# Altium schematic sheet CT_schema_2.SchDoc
size 523 x 486 mm
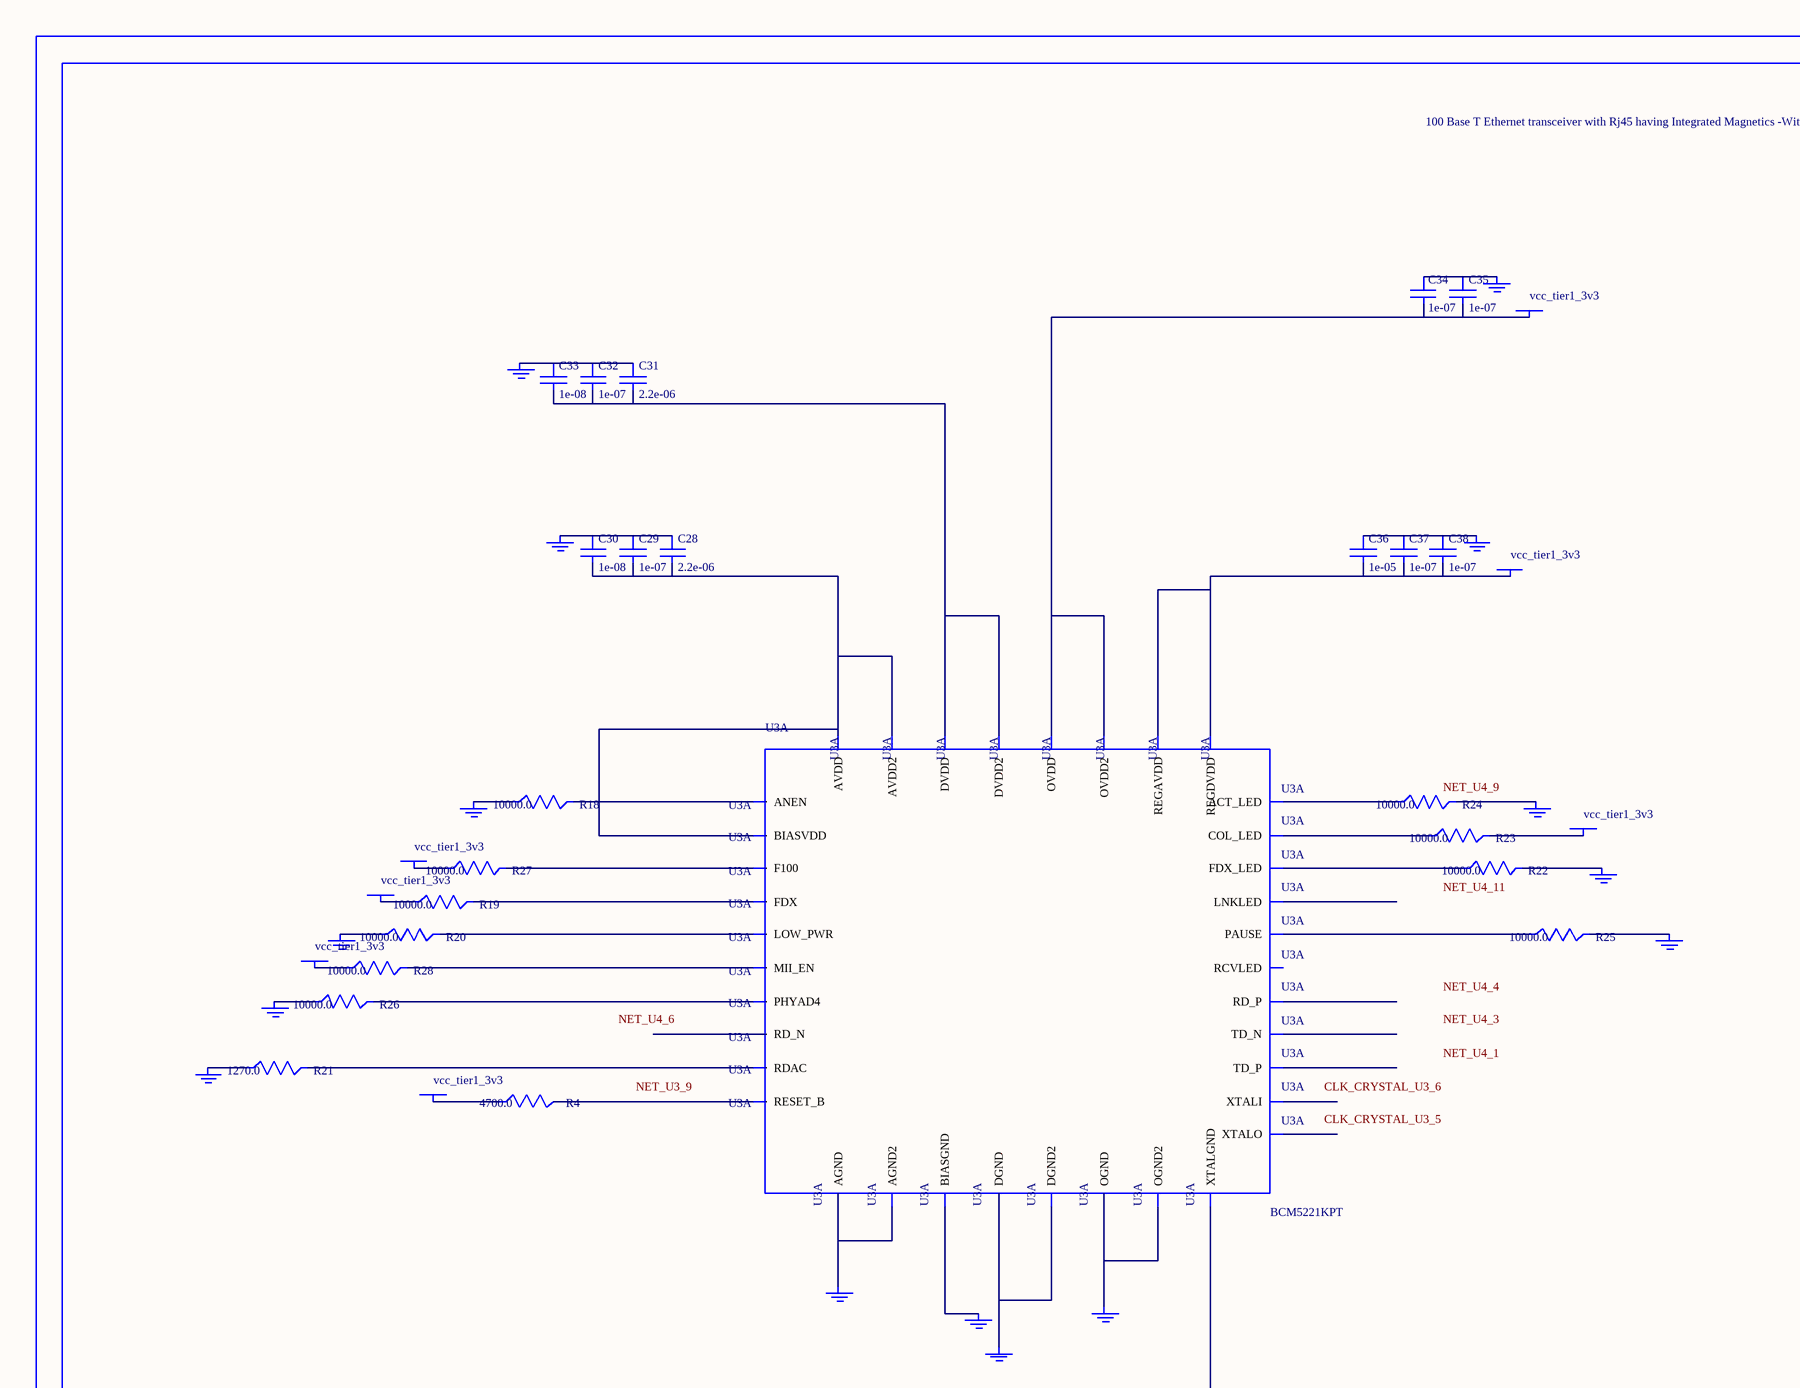
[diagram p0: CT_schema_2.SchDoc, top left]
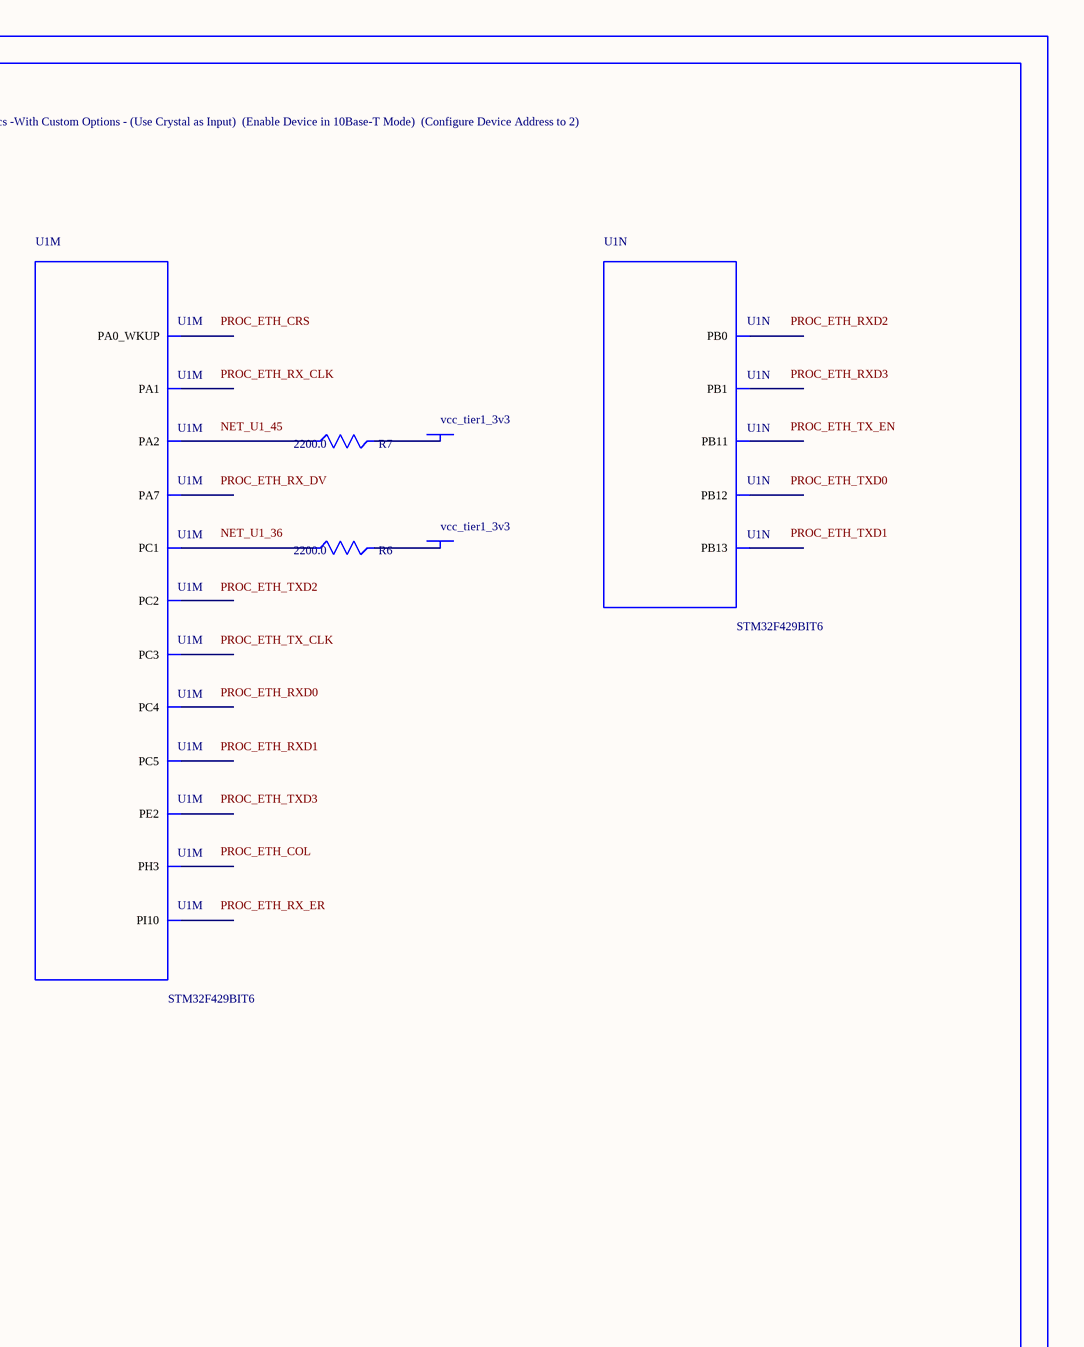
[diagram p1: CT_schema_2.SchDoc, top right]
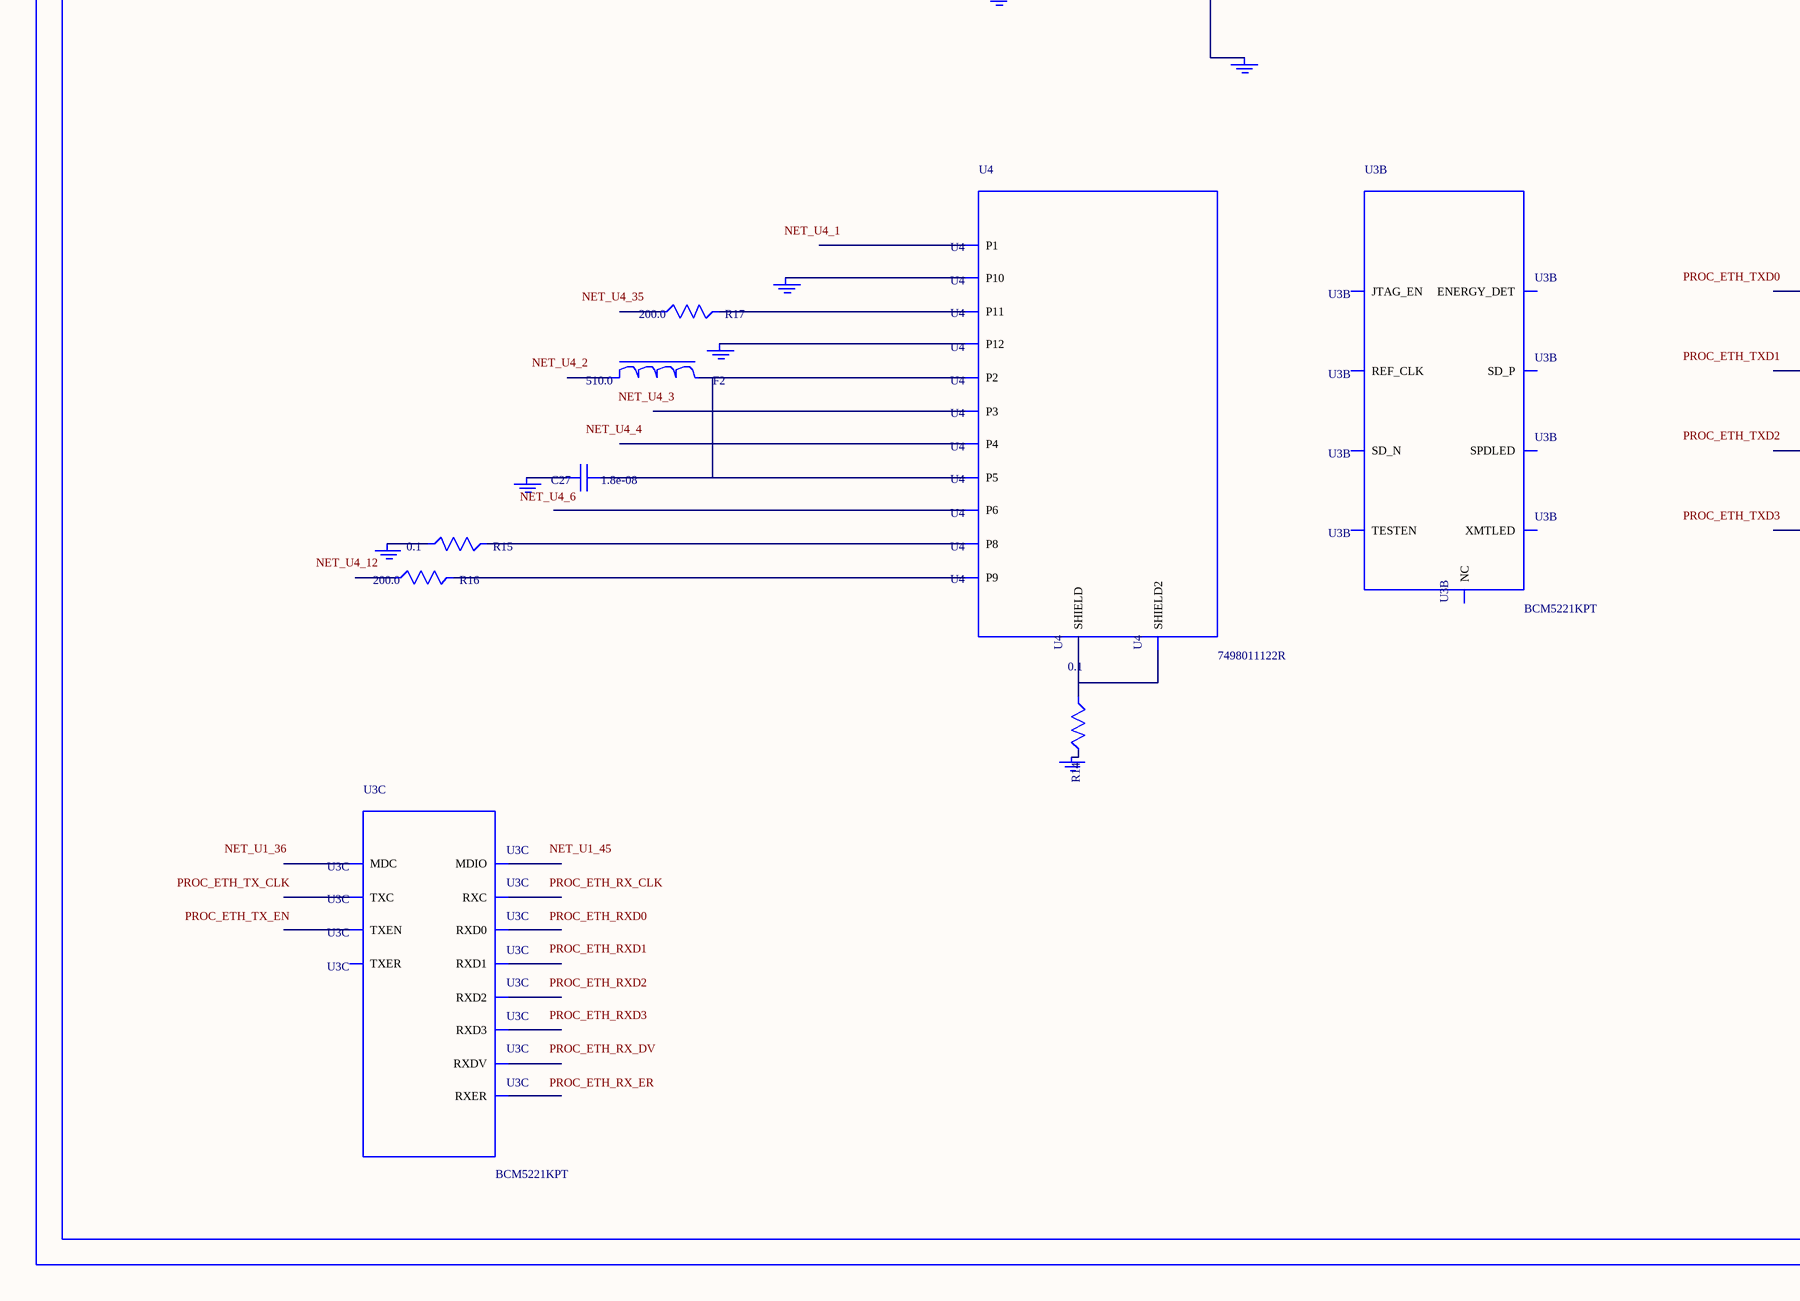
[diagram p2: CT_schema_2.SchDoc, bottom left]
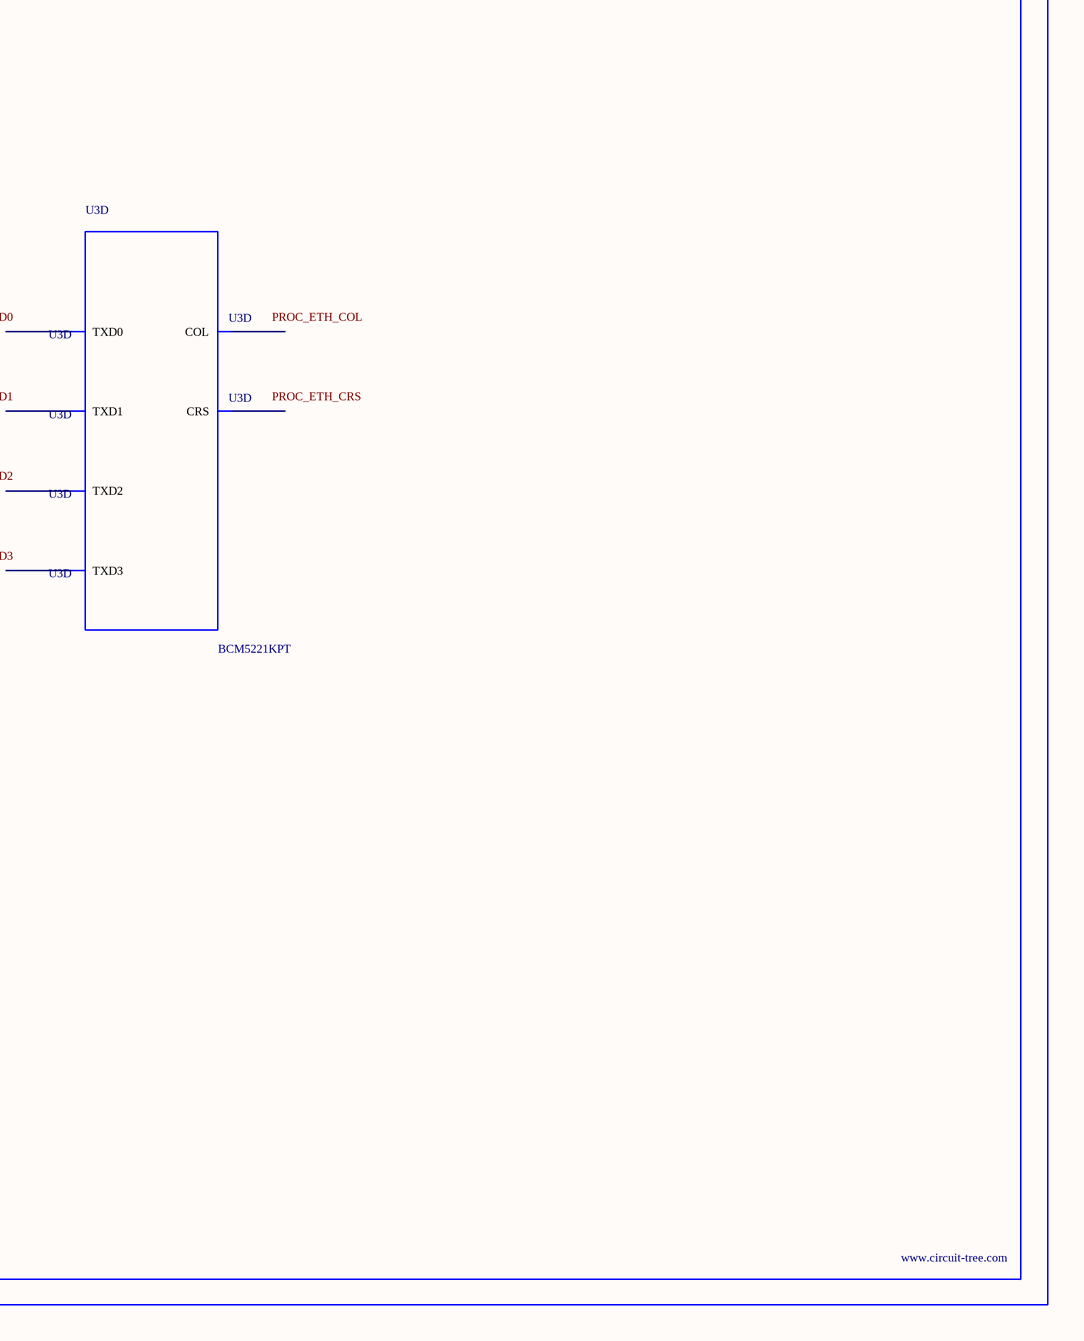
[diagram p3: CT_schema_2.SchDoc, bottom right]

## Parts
BORDER1  (no value)
C27  1.8e-08  [C0402]
C28  2.2e-06  [C0603]
C29  1e-07  [C0402]
C30  1e-08  [C0402]
C31  2.2e-06  [C0603]
C32  1e-07  [C0402]
C33  1e-08  [C0402]
C34  1e-07  [C0402]
C35  1e-07  [C0402]
C36  1e-05  [C0805]
C37  1e-07  [C0402]
C38  1e-07  [C0402]
F2  510.0  [L0603]
GND_INSTANCE_1_0  (no value)
GND_INSTANCE_1_1  (no value)
GND_INSTANCE_1_2  (no value)
GND_INSTANCE_1_3  (no value)
GND_INSTANCE_1_4  (no value)
GND_INSTANCE_1_5  (no value)
GND_INSTANCE_1_6  (no value)
GND_INSTANCE_1_7  (no value)
GND_INSTANCE_1_8  (no value)
GND_INSTANCE_1_9  (no value)
GND_INSTANCE_1_10  (no value)
GND_INSTANCE_1_11  (no value)
GND_INSTANCE_1_12  (no value)
GND_INSTANCE_1_13  (no value)
GND_INSTANCE_1_14  (no value)
GND_INSTANCE_1_15  (no value)
GND_INSTANCE_1_16  (no value)
GND_INSTANCE_1_17  (no value)
GND_INSTANCE_1_18  (no value)
GND_INSTANCE_1_19  (no value)
GND_INSTANCE_1_20  (no value)
POWER_INSTANCE_1_0  vcc_tier1_3v3
POWER_INSTANCE_1_1  vcc_tier1_3v3
POWER_INSTANCE_1_2  vcc_tier1_3v3
POWER_INSTANCE_1_3  vcc_tier1_3v3
POWER_INSTANCE_1_4  vcc_tier1_3v3
POWER_INSTANCE_1_5  vcc_tier1_3v3
POWER_INSTANCE_1_6  vcc_tier1_3v3
POWER_INSTANCE_1_7  vcc_tier1_3v3
POWER_INSTANCE_1_8  vcc_tier1_3v3
R4  4700.0  [R0603]
R6  2200.0  [R0603]
R7  2200.0  [R0603]
R14  0.1  [R0603]
R15  0.1  [R0603]
R16  200.0  [R0603]
R17  200.0  [R0603]
R18  10000.0  [R0603]
R19  10000.0  [R0603]
R20  10000.0  [R0603]
R21  1270.0  [R0603]
R22  10000.0  [R0603]
R23  10000.0  [R0603]
R24  10000.0  [R0603]
R25  10000.0  [R0603]
R26  10000.0  [R0603]
R27  10000.0  [R0603]
R28  10000.0  [R0603]
U1  STM32F429BIT6  [LQFP208]  (parts M,N of 16)
U3  BCM5221KPT  [TQFP64_10X10MC]  (parts A,B,C,D of 4)
U4  7498011122R  [7498011122R]

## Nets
NetC27_1: C27.1 F2.2 U4.2(P2) U4.5(P5)
NetC27_2: C27.2 GND_INSTANCE_1_16.0(GND)
NetC28_1: C28.1 C29.1 C30.1 GND_INSTANCE_1_11.0(GND)
NetC28_2: C28.2 C29.2 C30.2 U3.22(BIASVDD) U3.27(AVDD) U3.28(AVDD2)
NetC31_1: C31.1 C32.1 C33.1 GND_INSTANCE_1_1.0(GND)
NetC31_2: C31.2 C32.2 C33.2 U3.2(DVDD) U3.55(DVDD2)
NetC34_1: C34.1 C35.1 GND_INSTANCE_1_0.0(GND)
NetC34_2: C34.2 C35.2 POWER_INSTANCE_1_0.0(PWR) U3.1(OVDD) U3.46(OVDD2)
NetC36_1: C36.1 C37.1 C38.1 GND_INSTANCE_1_2.0(GND)
NetC36_2: C36.2 C37.2 C38.2 POWER_INSTANCE_1_1.0(PWR) U3.3(REGDVDD) U3.20(REGAVDD)
NetGND_INSTANCE_1_3_0: GND_INSTANCE_1_3.0(GND) U3.7(XTALGND)
NetGND_INSTANCE_1_4_0: GND_INSTANCE_1_4.0(GND) R22.2
NetGND_INSTANCE_1_5_0: GND_INSTANCE_1_5.0(GND) R24.2
NetGND_INSTANCE_1_6_0: GND_INSTANCE_1_6.0(GND) R25.2
NetGND_INSTANCE_1_7_0: GND_INSTANCE_1_7.0(GND) R26.1
NetGND_INSTANCE_1_8_0: GND_INSTANCE_1_8.0(GND) R20.1
NetGND_INSTANCE_1_9_0: GND_INSTANCE_1_9.0(GND) R21.1
NetGND_INSTANCE_1_10_0: GND_INSTANCE_1_10.0(GND) U3.24(BIASGND)
NetGND_INSTANCE_1_12_0: GND_INSTANCE_1_12.0(GND) R18.1
NetGND_INSTANCE_1_13_0: GND_INSTANCE_1_13.0(GND) U3.29(AGND) U3.32(AGND2)
NetGND_INSTANCE_1_14_0: GND_INSTANCE_1_14.0(GND) U3.40(OGND) U3.45(OGND2)
NetGND_INSTANCE_1_15_0: GND_INSTANCE_1_15.0(GND) U3.54(DGND) U3.63(DGND2)
NetGND_INSTANCE_1_17_0: GND_INSTANCE_1_17.0(GND) R15.1
NetGND_INSTANCE_1_18_0: GND_INSTANCE_1_18.0(GND) U4.10(P10)
NetGND_INSTANCE_1_19_0: GND_INSTANCE_1_19.0(GND) U4.12(P12)
NetGND_INSTANCE_1_20_0: GND_INSTANCE_1_20.0(GND) R14.2
NetPOWER_INSTANCE_1_2_0: POWER_INSTANCE_1_2.0(PWR) R23.2
NetPOWER_INSTANCE_1_3_0: POWER_INSTANCE_1_3.0(PWR) R28.1
NetPOWER_INSTANCE_1_4_0: POWER_INSTANCE_1_4.0(PWR) R27.1
NetPOWER_INSTANCE_1_5_0: POWER_INSTANCE_1_5.0(PWR) R19.1
NetPOWER_INSTANCE_1_6_0: POWER_INSTANCE_1_6.0(PWR) R4.1
NetPOWER_INSTANCE_1_7_0: POWER_INSTANCE_1_7.0(PWR) R6.2
NetPOWER_INSTANCE_1_8_0: POWER_INSTANCE_1_8.0(PWR) R7.2
NetR4_2: R4.2 U3.9(RESET_B)
NetR6_1: R6.1 U1.36(PC1)
NetR7_1: R7.1 U1.45(PA2)
NetR14_1: R14.1 U4.13(SHIELD) U4.14(SHIELD2)
NetR15_2: R15.2 U4.8(P8)
NetR16_2: R16.2 U4.9(P9)
NetR17_2: R17.2 U4.11(P11)
NetR18_2: R18.2 U3.38(ANEN)
NetR19_2: R19.2 U3.39(FDX)
NetR20_2: R20.2 U3.16(LOW_PWR)
NetR21_2: R21.2 U3.23(RDAC)
NetR22_1: R22.1 U3.10(FDX_LED)
NetR23_1: R23.1 U3.11(COL_LED)
NetR24_1: R24.1 U3.12(ACT_LED)
NetR25_1: R25.1 U3.13(PAUSE)
NetR26_2: R26.2 U3.14(PHYAD4)
NetR27_2: R27.2 U3.37(F100)
NetR28_2: R28.2 U3.18(MII_EN)

Not connected (* = marked no-connect by the designer): F2 1; R16 1; R17 1; U1 1(PE2) 12(PI10) 37(PC2) 38(PC3) 43(PA0_WKUP) 44(PA1) 47(PH3) 56(PA7) 57(PC4) 58(PC5) 61(PB0) 62(PB1) 91(PB11) 104(PB12) 105(PB13); U3 4(REF_CLK) 5(XTALO) 6(XTALI) 8(NC) 15(TESTEN) 17(ENERGY_DET) 19(SD_N) 21(SD_P) 25(RD_N) 26(RD_P) 30(TD_N) 31(TD_P) 33(RCVLED) 34(XMTLED) 35(LNKLED) 36(SPDLED) 41(MDIO) 42(MDC) 43(RXD3) 44(RXD2) 47(RXD1) 48(RXD0) 49(RXDV) 50(RXC) 51(RXER) 52(TXER) 53(TXC) 56(TXEN) 57(TXD0) 58(TXD1) 59(TXD2) 60(TXD3) 61(COL) 62(CRS) 64(JTAG_EN); U4 1(P1) 3(P3) 4(P4) 6(P6)

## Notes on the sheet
- Labels drawn without touching a wire or pin: CLK_CRYSTAL_U3_5, CLK_CRYSTAL_U3_6, NET_U1_36, NET_U1_45, NET_U3_9, NET_U4_1, NET_U4_2, NET_U4_3, NET_U4_4, NET_U4_6, NET_U4_9, NET_U4_11, NET_U4_12, NET_U4_35, PROC_ETH_COL, PROC_ETH_CRS, PROC_ETH_RX_CLK, PROC_ETH_RX_DV, PROC_ETH_RX_ER, PROC_ETH_RXD0, PROC_ETH_RXD1, PROC_ETH_RXD2, PROC_ETH_RXD3, PROC_ETH_TX_CLK, PROC_ETH_TX_EN, PROC_ETH_TXD0, PROC_ETH_TXD1, PROC_ETH_TXD2, PROC_ETH_TXD3

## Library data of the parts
BORDER1 = BORDER_PAGE1
C27 = C0402C183K3RAC
C28 C31 = C0603C225K8RACTU
C29 C32 C34 C35 C37 C38 = C0402C104K3RACTU
C30 C33 = C0402C103K3RAC
C36 = C0805C106K8RACTU
F2 = ERA3APB511V
GND_INSTANCE_1_0-GND_INSTANCE_1_20 = GND
POWER_INSTANCE_1_0-POWER_INSTANCE_1_8 = PWR
R4 = RC0603JR-074K7L
R6 R7 = RC0603JR-072K2L
R14 R15 = ERJ-3RSFR10V
R16 R17 = RC0603JR-07200RL
R18-R20 R22-R28 = RC0603JR-0710KL
R21 = RC0603FR-071K27L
